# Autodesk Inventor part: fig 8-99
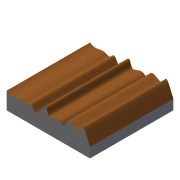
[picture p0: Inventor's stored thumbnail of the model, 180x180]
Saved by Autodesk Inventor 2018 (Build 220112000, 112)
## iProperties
Shininess: 64.0
Length Units: 11269
Angle Units: 11279
Time Units: 11290
Mass Units: 11283
Length Display Precision: 3
Angle Display Precision: 2
Compacted: True
Part Number: fig 8-99
Document SubType Name: Modeling
Created: 2002-12
Designer: deepak
Density: 1 g/cm^3
Material: Generic
Appearance: Default
Density: 0.0
Volumn: 0.0
Area: 0.0
PropertySet Name: Model Information
Control State: 0
Master: False
Checked Out: False
Author: deepak
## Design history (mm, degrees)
sketch "Sketch1"
  geometry: L1 (-32.188, 30.089)-(27.812, 30.089); L2 (27.812, 30.089)-(27.812, -29.911); L3 (27.812, -29.911)-(-32.188, -29.911); L4 (-32.188, -29.911)-(-32.188, 30.089)
  constraints: 8 end point, 2 parallel, 1 horizontal, 1 perpendicular
  dimensions: "d0" = 60 distance of L1.start L1.end; "d1" = 60 distance of L3.end L1.start
extrude "Extrusion1" new body sketch "Sketch1" stored distance "d2" = 20; taper "d3" = 0 deg
sketch "Sketch2"
  geometry: 17 further points
  constraints: 17 other
extrude_surface "ExtrusionSrf1" sketch "Sketch2" dims "d4" = 70, "d5" = 0
split "Split1"
body "Solid1"
body "Srf1"
